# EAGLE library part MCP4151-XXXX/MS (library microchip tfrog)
MCP4151 7/8-Bit Single SPI Digital Potentiometer with Volatile Memory Doc: http://www.microchip.com/wwwproducts/Devices.aspx?dDocName=en531890 Ref Used: MCP4151-104E/MS (8 bits, 100K ohms)
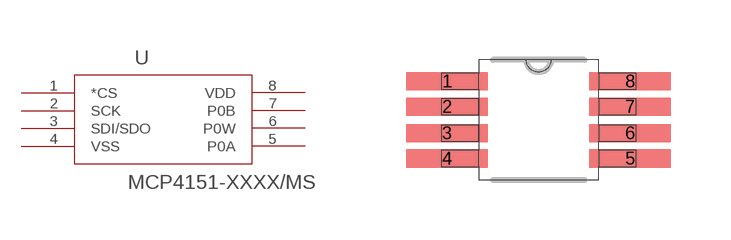
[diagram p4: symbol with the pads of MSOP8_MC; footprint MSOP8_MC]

Designator prefix -

## MCP4151-XXXX/MS  [MSOP8_MC]
1  *CS  pas
2  SCK  pas
3  SDI/SDO  pas
4  VSS  pas
5  P0A  pas
6  P0W  pas
7  P0B  pas
8  VDD  pas

## Footprint MSOP8_MC (pad centres in mm)
MSOP8 with long pads (0.08inch instead of 0.06)
smd 2.032 x 0.457: 1 -2.286,0.965; 2 -2.286,0.33; 3 -2.286,-0.33; 4 -2.286,-0.965; 5 2.286,-0.965; 6 2.286,-0.33; 7 2.286,0.33; 8 2.286,0.965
